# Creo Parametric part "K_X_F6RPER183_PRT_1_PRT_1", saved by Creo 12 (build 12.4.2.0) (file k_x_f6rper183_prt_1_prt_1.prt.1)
Units: Custom; MM, KILOGRAM, SECS

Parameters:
  PTC_WM_ITERATION = "0"
  PTC_WM_VERSION = "-.0"
  PTC_WM_LIFECYCLE_STATE = "In Work"
  PTC_WM_LIFECYCLE = "MO_CADDocument"
  PTC_WM_CREATED_BY = "Maximilian Roepper (Z0017RMS: MO)"
  PTC_WM_CREATED_ON = "18-Sep-26 11:36:42 AM"
  PTC_WM_MODIFIED_BY = "Maximilian Roepper (Z0017RMS: MO)"
  PTC_WM_MODIFIED_ON = "18-Sep-26 11:36:46 AM"
  PDMLINKNUMBER = "PDM000071454822"
  PTC_WM_NAME = "k_x_f6rper183_prt_1_prt_1.prt"
  PTC_WM_NUMBER = "PDM000071454822"

Other parameters: WEIGHT, WEIGHT_FACTOR, WEIGHT_ADD, _MASS_TEMP, _DIFF_TEMP, MC_ERRORS, SUPPLIER

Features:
  1. coordinate system
  2. datum plane "PRT_YZ"
  3. datum plane "PRT_XY"
  4. datum plane "PRT_XZ"
  5. coordinate system
  6. datum axis
  7. datum axis
  8. datum axis
  9. coordinate system
  10. imported feature
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
Other named items: PRT, SIEMENS_MO, DRW_VIEW_ORG, PRT_X, PRT_Y, PRT_Z, CS0, ROUGH_GROB

Layers: 00_STD_CSYS-KSYS, 01_STD_PLANES-EBENEN, 02_STD_AXES-ACHSEN, 03_STD_CSYS-KSYS, 24_IMPORT_FEAT-IMPORT_KE

Surfaces: 18 tabulated cylinder, 8 plane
